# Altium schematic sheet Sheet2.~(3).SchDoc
size A3
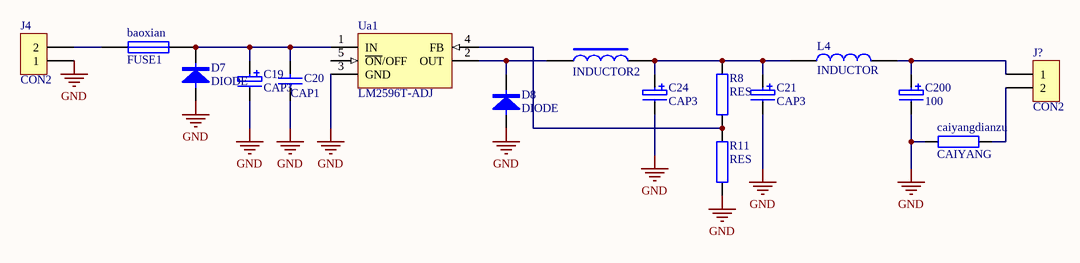
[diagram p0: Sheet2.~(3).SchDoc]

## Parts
?  INDUCTOR2
baoxian  FUSE1  [RAD0.5]
C19  CAP3  [RB2]
C20  CAP1  [RAD0.2]
C21  CAP3  [RB3]
C24  CAP3  [RB3]
C200  100  [RB1]
caiyangdianzu  CAIYANG  [AXIAL0.8]
D7  DIODE  [DIODE0.4]
D8  DIODE  [DIODE0.2]
J4  CON2  [BCON2]
J?  CON2  [BCON2]
L4  INDUCTOR  [LHF440]
R8  RES  [AXIAL0.3]
R11  RES  [AXIAL0.3]
Ua1  LM2596T-ADJ  [SIP-5]

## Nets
GND: C19.2 C20.2 C21.2 C24.2 C200.2 caiyangdianzu.2 D7.1 D8.1 J4.1 R11.1 Ua1.3(GND)
Net?_1: ?.1 D8.2 Ua1.2(OUT)
Net?_2: ?.2 C21.1 C24.1 L4.1 R8.2
Netbaoxian_1: baoxian.1 C19.1 C20.1 D7.2 Ua1.1(IN)
Netbaoxian_2: baoxian.2 J4.2
NetC200_1: C200.1 J?.1 L4.2
Netcaiyangdianzu_1: caiyangdianzu.1 J?.2
NetR8_1: R8.1 R11.2 Ua1.4(FB)

Not connected (* = marked no-connect by the designer): Ua1 5(~{ON}/OFF)

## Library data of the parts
baoxian = FUSE1: Fuse
C200 = CAP3
caiyangdianzu = RES
J4 J? = CON2: Connector
Ua1 = LM2596T-5.0: Simple Switcher Power Converter 150 kHz 3A Step Down Voltage Regulator; PackageDocument: 2000; Note: Tab is connected to GND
